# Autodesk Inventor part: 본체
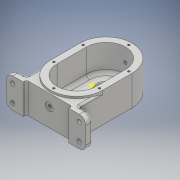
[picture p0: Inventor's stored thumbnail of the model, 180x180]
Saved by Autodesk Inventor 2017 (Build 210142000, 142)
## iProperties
Part Number: 본체
Material: 일반
Document SubType Name: Modeling
Designer: MRC
Density: 1 g/cm^3
Appearance: 기본값
Author: MRC
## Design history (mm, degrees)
sketch "스케치1"
  geometry: L1 (0, -22.5)-(0, 22.5); L2 (40, -22.5)-(40, 22.5); L3 (-40, 22.5)-(-40, -22.5); A1 r 40 centre (0, -22.5) between (-40, -22.5) and (40, -22.5); A2 r 40 centre (0, 22.5) between (40, 22.5) and (-40, 22.5); 1 further point
  constraints: 8 end point, 4 point on circle, 4 tangent, 2 centre point, 1 midpoint, 1 parallel, 1 vertical
  dimensions: "d0" = 80 distance between parallel lines of L2 L3; "d1" = 45 distance of L1.start L1.end
extrude "돌출1" new body sketch "스케치1" stored distance "d2" = 49; taper "d3" = 0 deg
sketch "스케치2"
  geometry: L1 (40, -22.5)-(40, 22.5) reference; L2 (-40, 22.5)-(-40, -22.5) reference; L3 (30, 22.5)-(30, -22.5); L4 (-30, -22.5)-(-30, 22.5); A1 r 40 centre (0, 22.5) between (40, 22.5) and (-40, 22.5) reference; A2 r 40 centre (0, -22.5) between (-40, -22.5) and (40, -22.5) reference; A3 r 30 centre (0, 22.5) between (30, 22.5) and (-30, 22.5); A4 r 30 centre (0, -22.5) between (-30, -22.5) and (30, -22.5)
  constraints: 4 end point, 4 point on circle, 2 centre point, 3 other
  dimensions: "d5" = 10 radial gap between concentric circles of A1 A3
extrude "돌출2" cut sketch "스케치2" distance "d6" = 41; taper "d7" = 0 deg
sketch "스케치5"
  geometry: L1 (0, -22.5)-(0, 22.5); L2 (-26, -22.5)-(-26, 22.5); L3 (26, 22.5)-(26, -22.5); A1 r 26 centre (0, -22.5) between (-26, -22.5) and (26, -22.5); A2 r 26 centre (0, 22.5) between (26, 22.5) and (-26, 22.5); 1 further point
  constraints: 8 end point, 4 point on circle, 4 tangent, 2 centre point, 1 midpoint, 1 parallel, 1 vertical
  dimensions: "d15" = 52 distance between parallel lines of L3 L2; "d16" = 45 distance of L1.start L1.end
extrude "돌출3" join sketch "스케치5" distance "d17" = 11; taper "d18" = 0 deg
sketch "스케치6"
  geometry: L1 (-26, -7.5)-(26, -7.5); L2 (-26, -22.5)-(-26, 22.5) reference; L3 (-26, 22.5)-(-26, -7.5); L4 (26, 22.5)-(26, -22.5) reference; L5 (26, -7.5)-(26, 22.5); A1 r 26 centre (0, 22.5) between (26, 22.5) and (-26, 22.5) reference; A2 r 26 centre (0, 22.5) between (26, 22.5) and (-26, 22.5) reference; A3 r 26 centre (0, 22.5) between (26, 22.5) and (-26, 22.5); 1 further point
  constraints: 6 end point, 2 point on circle, 2 point on line, 1 centre point, 1 coincident, 1 collinear, 1 horizontal
  dimensions: "d19" = 30 distance from line of L1 A1.centre
extrude "돌출4" cut sketch "스케치6" distance "d20" = 3; taper "d21" = 0 deg
hole "구멍2" diameter "d24" = 22; stored, may be unused: countersink angle "d28" = 90 deg, drill point angle "d30" = 0 deg; dims "d25" = 6, "d26" = 28, "d27" = 4, "d29" = 4, "d31" = 10, "d32" = 10
hole "구멍3" diameter "d35" = 28; stored, may be unused: countersink angle "d39" = 90 deg, drill point angle "d41" = 118 deg; dims "d33" = 10, "d34" = 10, "d36" = 6, "d37" = 4, "d38" = 2, "d40" = 8
hole "구멍5" diameter "d53" = 20; stored, may be unused: countersink angle "d57" = 90 deg, drill point angle "d59" = 0 deg; dims "d51" = 10, "d52" = 10, "d54" = 6, "d55" = 28, "d56" = 8, "d58" = 12
node "작업 평면2"
sketch "스케치8"
  geometry: L1 (40, 24.5)-(-40, 24.5) reference; C1 r 6 at (0, 3.5); 1 further point
  constraints: 1 centre point, 1 vertical alignment
  dimensions: "d70" = 12 diameter of C1; "d71" = 21 distance from line of C1.centre L1
extrude "돌출5" join sketch "스케치8" stored distance "d62" = 3; taper "d63" = 0 deg
fillet "모깎기4" dims "d88" = 5
fillet "모깎기5" dims "d89" = 3
sketch "스케치12" dims "d90" = 40
  geometry: C1 r 14 at (0, 22.5) reference; C2 r 11 at (0, 22.5) reference; 3 further points
  constraints: 2 vertical alignment, 1 coincident, 2 other
hole "구멍7" sketch "스케치12" at (0, 42.5) diameter "d91" = 3.242; stored, may be unused: countersink angle "d95" = 90 deg, drill point angle "d97" = 118 deg; dims "d92" = 8, "d93" = 28, "d94" = 8, "d96" = 10
sketch "스케치15"
  geometry: L1 (40, -22.5)-(40, -59.5); L2 (40, -59.5)-(61, -59.5); L3 (61, -59.5)-(61, -69.5); L4 (61, -69.5)-(35, -69.5); L5 (35, -69.5)-(35, -64.5); L6 (35, -64.5)-(-35, -64.5); L7 (-35, -69.5)-(-61, -69.5); L8 (-61, -69.5)-(-61, -59.5); L9 (-61, -59.5)-(-40, -59.5); L10 (-40, 22.5)-(-40, -22.5) reference; L11 (-40, -59.5)-(-40, -22.5); L12 (-35, -64.5)-(-35, -69.5); C1 r 11 at (0, 22.5) reference; A1 r 40 centre (0, -22.5) between (-40, -22.5) and (40, -22.5) reference; A2 r 40 centre (0, -22.5) between (-40, -22.5) and (40, -22.5) reference; 1 further point
  constraints: 22 end point, 3 horizontal, 3 vertical, 2 collinear, 2 perpendicular, 2 tangent, 1 parallel
  dimensions: "d132" = 10 distance of L2.end L3.end; "d133" = 35 distance from line of L5 C1.centre; "d134" = 70 distance of L5.end L6.end; "d135" = 5 distance of L6.end L7.start; "d136" = 92 distance from line of C1.centre L7; "d137" = 122 distance between parallel lines of L3 L8; "d138" = 61 distance from line of C1.centre L8
extrude "돌출9" join sketch "스케치15" distance "d139" = 46; taper "d140" = 0 deg
fillet "모깎기6" dims "d141" = 10
fillet "모깎기7" dims "d142" = 3
fillet "모깎기8" dims "d143" = 3
fillet "모깎기9" dims "d144" = 3
sketch "스케치16"
  geometry: L1 (72, 49)-(-8, 49) reference; 2 further points
  constraints: 1 vertical alignment
  dimensions: "d145" = 21 distance from line of point (32, 28) L1
hole "구멍11" sketch "스케치16" at (32, 28) diameter "d146" = 4.917; stored, may be unused: countersink angle "d150" = 90 deg, drill point angle "d152" = 0 deg; dims "d147" = 135, "d148" = 12, "d149" = 1, "d151" = 17.1
sketch "스케치17"
  geometry: A1 r 7 centre (7, 26) between (7, 33) and (0, 26) reference; A2 r 10 centre (7, 0) between (-3, 0) and (7, -10) reference; A3 r 10 centre (109, 26) between (119, 26) and (109, 36) reference; A4 r 10 centre (109, 0) between (109, -10) and (119, 0) reference; 5 further points
  constraints: 4 coincident
hole "구멍12" sketch "스케치17" at (7, 26), (7, 0), (109, 26), (109, 0) diameter "d153" = 6.6; stored, may be unused: countersink angle "d157" = 90 deg, drill point angle "d159" = 0 deg; dims "d154" = 10, "d155" = 11, "d156" = 2, "d158" = 17.1
sketch "스케치18"
  geometry: L1 (-30, -22.5)-(-30, 22.5) reference; L2 (30, 22.5)-(30, -22.5) reference; L3 (40, -22.5)-(40, 22.5) reference; L4 (-40, 22.5)-(-40, -22.5) reference; L5 (35, 22.5)-(35, -22.5); L6 (-35, -22.5)-(-35, 22.5); A1 r 30 centre (0, 22.5) between (30, 22.5) and (-30, 22.5) reference; A2 r 30 centre (0, -22.5) between (-30, -22.5) and (30, -22.5) reference; A3 r 40 centre (0, 22.5) between (40, 22.5) and (-40, 22.5) reference; A4 r 40 centre (0, -22.5) between (-40, -22.5) and (40, -22.5) reference; A5 r 35 centre (0, 22.5) between (35, 22.5) and (-35, 22.5); A6 r 35 centre (0, -22.5) between (-35, -22.5) and (35, -22.5); 8 further points
  constraints: 7 point on circle, 4 coincident, 4 end point, 2 centre point, 2 horizontal alignment, 3 other
  dimensions: "d160" = 5 radial gap between concentric circles of A3 A5
hole "구멍13" sketch "스케치18" at (-35, 22.5), (-35, -22.5), (0, -57.5), (35, -22.5), (35, 22.5), (0, 57.5) diameter "d161" = 3.242; stored, may be unused: countersink angle "d165" = 90 deg, drill point angle "d167" = 118 deg; dims "d162" = 8, "d163" = 28, "d164" = 8, "d166" = 10
sketch "스케치19"
  geometry: L1 (-51, -69.5)-(-35, -69.5) reference; 2 further points
  constraints: 1 vertical alignment, 1 other
  dimensions: "d168" = 12 distance from line of L1 point (0, -57.5)
feature "엠보싱1" sketch "스케치19" dims "d169" = 0.5, "d170" = 0
fillet "모깎기10" dims "d171" = 0.3
fillet "모깎기12" dims "d173" = 3
fillet "모깎기13" dims "d174" = 0.3
chamfer "모따기1" distance "d175" = 1; stored, may be unused: second distance "d176" = 2, angle "d177" = 45 deg
node "솔리드1"
pattern_circular "원형 패턴1" dims angle "d99" = 360 deg
node "투영된 루프1"
node "투영된 루프4"
node "투영된 루프7"
